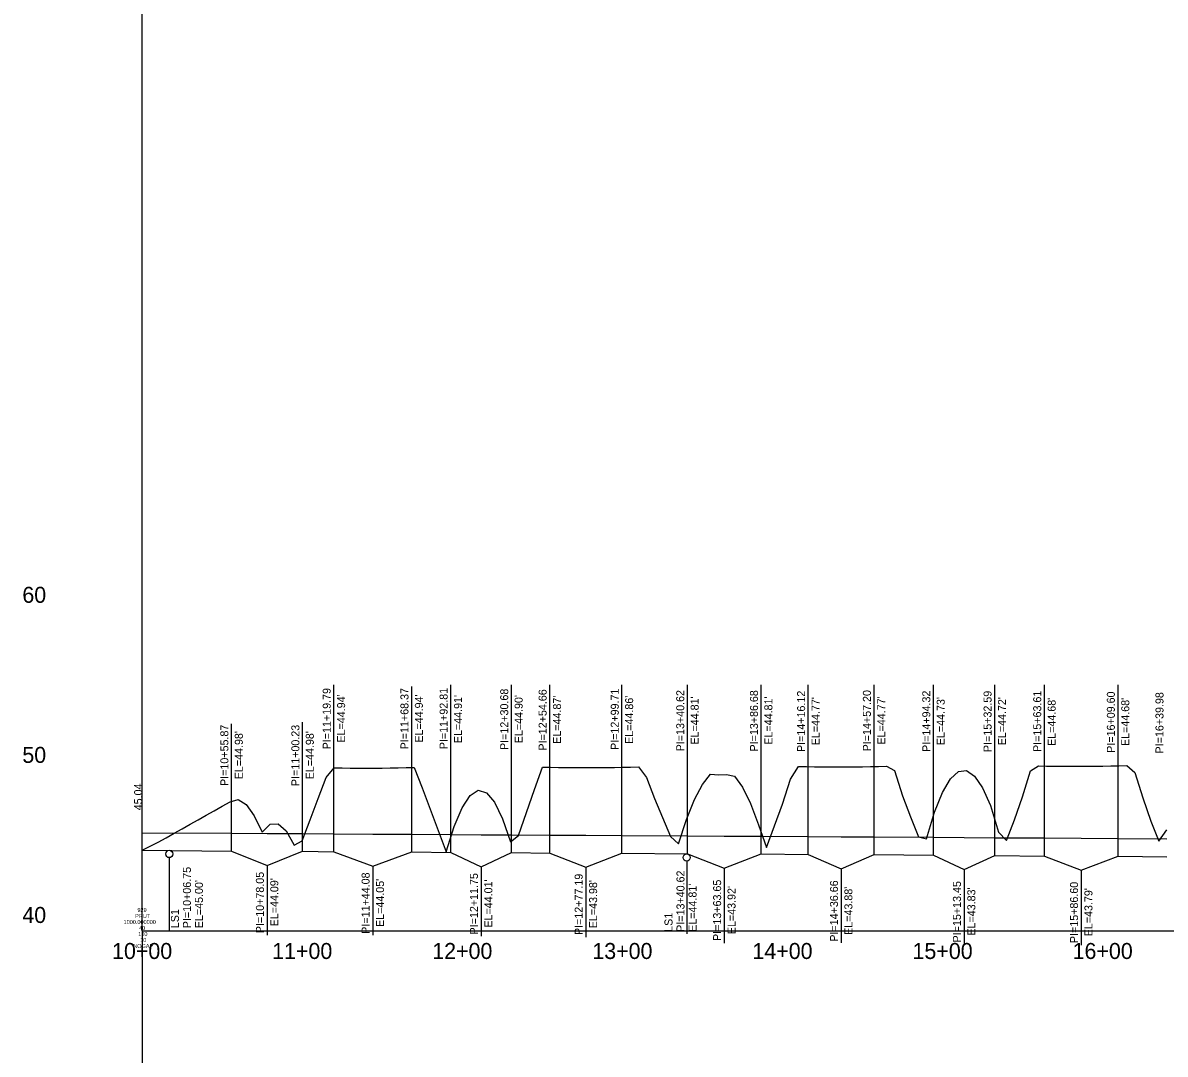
# Model space of a CAD drawing. Extents: x 2394206 to 2397081, y 556531 to 561531.
# Drawn here: x 2394206 to 2394920, y 558954 to 559598 of the extents above; entities that cross this region are included whole.
import ezdxf

# ---------------------------------------------------------------- set-up
doc = ezdxf.new("R2010")
doc.units = 0
for name, color, linetype in [('Default', 7, 'Continuous'), ('Existing ground', 7, 'Continuous'), ('Profile grid', 7, 'Continuous'), ('Proposed bankfull', 7, 'Continuous'), ('Proposed structure lables', 7, 'Continuous'), ('Station lables', 7, 'Continuous')]:
    doc.layers.add(name, color=color, linetype=linetype)

msp = doc.modelspace()

# ---------------------------------------------------------------- linework, layer by layer
at = {"layer": 'Default'}
for p, q in [((2394400.63, 559080.63), (2394400.63, 559185.03)), ((2394449.21, 559080.58), (2394449.21, 559183.93)), ((2394473.65, 559080.25), (2394473.65, 559185.03)), ((2394511.52, 559080.21), (2394511.52, 559185.03)), ((2394535.5, 559079.85), (2394535.5, 559185.03)), ((2394580.55, 559079.8), (2394580.55, 559185.03)), ((2394621.46, 559079.33), (2394621.46, 559185.03)), ((2394667.52, 559079.28), (2394667.52, 559185.03)), ((2394696.96, 559078.91), (2394696.96, 559185.03)), ((2394738.04, 559078.87), (2394738.04, 559185.03)), ((2394775.16, 559078.46), (2394775.16, 559185.03)), ((2394813.43, 559078.42), (2394813.43, 559185.03)), ((2394844.45, 559078.01), (2394844.45, 559185.03)), ((2394890.44, 559077.96), (2394890.44, 559185.03)), ((2394336.71, 559081.03), (2394336.71, 559160.51)), ((2394381.07, 559080.99), (2394381.07, 559161.61)), ((2394358.89, 559072.12), (2394358.89, 559028.6)), ((2394424.92, 559071.73), (2394424.92, 559028.6)), ((2394492.59, 559071.33), (2394492.59, 559028.01)), ((2394558.03, 559070.94), (2394558.03, 559027.42)), ((2394644.49, 559070.42), (2394644.49, 559023.52)), ((2394717.5, 559069.99), (2394717.5, 559023.72)), ((2394794.29, 559069.53), (2394794.29, 559022.54)), ((2394867.44, 559069.1), (2394867.44, 559022.35))]:
    msp.add_line(p, q, dxfattribs=at)
at = {"layer": 'Existing ground'}
for points in [[(2394280.84, 559081.62), (2394285.84, 559084.14), (2394290.84, 559086.66), (2394295.84, 559089.37), (2394300.84, 559092.19), (2394305.84, 559095.01), (2394310.84, 559097.82), (2394315.84, 559100.64), (2394320.84, 559103.46), (2394325.84, 559106.27), (2394330.84, 559109.09), (2394335.84, 559111.91), (2394340.84, 559113.23), (2394345.84, 559110.24), (2394350.84, 559103.04), (2394355.84, 559093.01), (2394360.84, 559097.82), (2394365.84, 559098.04), (2394370.84, 559093.64), (2394375.84, 559084.85), (2394380.84, 559087.52), (2394385.84, 559100.69), (2394390.84, 559113.85), (2394395.84, 559127.01), (2394400.84, 559133.12), (2394405.84, 559133.05), (2394410.84, 559132.99), (2394415.84, 559132.96), (2394420.84, 559132.95), (2394425.84, 559132.96), (2394430.84, 559132.99), (2394435.84, 559133.04), (2394440.84, 559133.12), (2394445.84, 559133.21), (2394450.84, 559133.31), (2394455.84, 559120.68), (2394460.84, 559107.32), (2394465.84, 559093.96), (2394470.84, 559080.67), (2394475.84, 559096.49), (2394480.84, 559108.21), (2394485.84, 559115.86), (2394490.84, 559119.04), (2394495.84, 559117.58), (2394500.84, 559111.57), (2394505.84, 559101.31), (2394510.84, 559086.78), (2394515.84, 559090.82), (2394520.84, 559105.21), (2394525.84, 559119.6), (2394530.84, 559133.52), (2394535.84, 559133.42), (2394540.84, 559133.34), (2394545.84, 559133.27), (2394550.84, 559133.23), (2394555.84, 559133.21), (2394560.84, 559133.22), (2394565.84, 559133.24), (2394570.84, 559133.3), (2394575.84, 559133.37), (2394580.84, 559133.46), (2394585.84, 559133.56), (2394590.84, 559133.66), (2394595.84, 559127.04), (2394600.84, 559113.87), (2394605.84, 559101.99), (2394610.84, 559090.12), (2394615.84, 559085.7), (2394620.84, 559100.88), (2394625.84, 559113.22), (2394630.84, 559122.71), (2394635.84, 559129.04), (2394640.84, 559128.77), (2394645.84, 559128.92), (2394650.84, 559127.98), (2394655.84, 559120.94), (2394660.84, 559110.81), (2394665.84, 559097.42), (2394670.84, 559083.42), (2394675.84, 559096.94), (2394680.84, 559110.46), (2394685.84, 559126.06), (2394690.84, 559133.93), (2394695.84, 559133.84), (2394700.84, 559133.76), (2394705.84, 559133.7), (2394710.84, 559133.66), (2394715.84, 559133.65), (2394720.84, 559133.67), (2394725.84, 559133.71), (2394730.84, 559133.77), (2394735.84, 559133.86), (2394740.84, 559133.96), (2394745.84, 559134.06), (2394750.84, 559131.41), (2394755.84, 559115.64), (2394760.84, 559102.49), (2394765.84, 559090.01), (2394770.84, 559088.69), (2394775.84, 559105.44), (2394780.84, 559117.72)], [(2394780.84, 559117.72), (2394785.84, 559126.23), (2394790.84, 559130.88), (2394795.84, 559131.47), (2394800.84, 559127.99), (2394805.84, 559120.58), (2394810.84, 559109.53), (2394815.84, 559092.82), (2394820.84, 559087.8), (2394825.84, 559100.69), (2394830.84, 559114.92), (2394835.84, 559131.32), (2394840.84, 559134.32), (2394845.84, 559134.24), (2394850.84, 559134.17), (2394855.84, 559134.12), (2394860.84, 559134.1), (2394865.84, 559134.09), (2394870.84, 559134.11), (2394875.84, 559134.15), (2394880.84, 559134.21), (2394885.84, 559134.29), (2394890.84, 559134.39), (2394895.84, 559134.49), (2394900.84, 559130.13), (2394905.84, 559114.33), (2394910.84, 559099.75), (2394915.84, 559087.24), (2394920.84, 559094.41)]]:
    msp.add_lwpolyline(points, dxfattribs=at)
at = {"layer": 'Profile grid'}
for q in [(2394280.84, 561531.18), (2397080.84, 559031.18), (2394280.84, 556531.18)]:
    msp.add_line((2394280.84, 559031.18), q, dxfattribs=at)
at = {"layer": 'Proposed bankfull'}
msp.add_lwpolyline([(2394280.84, 559092.58), (2394336.71, 559092.26), (2394358.89, 559092.13), (2394381.07, 559092), (2394400.63, 559091.88), (2394424.92, 559091.74), (2394449.21, 559091.6), (2394473.65, 559091.45), (2394492.59, 559091.34), (2394511.52, 559091.23), (2394535.5, 559091.09), (2394558.03, 559090.96), (2394580.55, 559090.83), (2394621.46, 559090.59), (2394644.49, 559090.45), (2394667.52, 559090.32), (2394696.96, 559090.14), (2394717.5, 559090.02), (2394738.04, 559089.9), (2394775.16, 559089.69), (2394794.29, 559089.57), (2394813.43, 559089.46), (2394844.45, 559089.28), (2394867.44, 559089.14), (2394890.44, 559089.01), (2394920.82, 559088.83)], dxfattribs=at)
at = {"layer": 'Proposed structure lables'}
for p, q in [((2394280.84, 559081.58), (2394336.71, 559081.03)), ((2394297.76, 559077), (2394297.76, 559031.62)), ((2394336.71, 559081.03), (2394358.89, 559072.12)), ((2394358.89, 559072.12), (2394381.07, 559080.99)), ((2394381.07, 559080.99), (2394400.63, 559080.63)), ((2394400.63, 559080.63), (2394424.92, 559071.73)), ((2394424.92, 559071.73), (2394449.21, 559080.58)), ((2394449.21, 559080.58), (2394473.65, 559080.25)), ((2394473.65, 559080.25), (2394492.59, 559071.33)), ((2394492.59, 559071.33), (2394511.52, 559080.21)), ((2394511.52, 559080.21), (2394535.5, 559079.85)), ((2394535.5, 559079.85), (2394558.03, 559070.94)), ((2394558.03, 559070.94), (2394580.55, 559079.8)), ((2394580.55, 559079.8), (2394621.46, 559079.33)), ((2394620.98, 559074.74), (2394620.98, 559029.37)), ((2394621.46, 559079.33), (2394644.49, 559070.42)), ((2394644.49, 559070.42), (2394667.52, 559079.28)), ((2394667.52, 559079.28), (2394696.96, 559078.91)), ((2394696.96, 559078.91), (2394717.5, 559069.99)), ((2394717.5, 559069.99), (2394738.04, 559078.87)), ((2394738.04, 559078.87), (2394775.16, 559078.46)), ((2394775.16, 559078.46), (2394794.29, 559069.53)), ((2394794.29, 559069.53), (2394813.43, 559078.42)), ((2394813.43, 559078.42), (2394844.45, 559078.01)), ((2394844.45, 559078.01), (2394867.44, 559069.1)), ((2394867.44, 559069.1), (2394890.44, 559077.96)), ((2394890.44, 559077.96), (2394920.82, 559077.56))]:
    msp.add_line(p, q, dxfattribs=at)
for centre in [(2394297.76, 559079.29), (2394620.98, 559077.04)]:
    msp.add_ellipse(centre, major_axis=(0, -2.29), ratio=0.950348, dxfattribs=at)

# ---------------------------------------------------------------- texts
at = {"layer": 'Profile grid'}
for s, height, p in [('     60', 10, (2394187.44, 559236.18)), ('     50', 10, (2394187.44, 559136.18)), ('     40', 10, (2394187.44, 559036.18)), ('PRUT', 2.5, (2394276.47, 559039.31)), ('929', 2.5, (2394277.89, 559043.06)), ('1000.000000', 2.5, (2394269.25, 559035.56)), ('40', 2.5, (2394278.91, 559031.81)), ('100', 2.5, (2394278.4, 559028.06)), ('10', 2.5, (2394279.62, 559024.31)), ('NOGAP', 2.5, (2394275.27, 559020.56))]:
    msp.add_text(s, height=height, dxfattribs=at).set_placement(p)
at = {"layer": 'Proposed structure lables'}
for s, p in [('PI=11+19.79', (2394398.63, 559144.65)), ('PI=11+68.37', (2394447.21, 559144.65)), ('PI=11+92.81', (2394471.65, 559144.74)), ('PI=12+30.68', (2394509.52, 559144.23)), ('PI=12+54.66', (2394533.5, 559143.87)), ('PI=12+99.71', (2394578.55, 559144.29)), ("EL=44.94'", (2394407.63, 559148.9)), ("EL=44.94'", (2394456.21, 559148.85)), ("EL=44.91'", (2394480.65, 559148.52)), ("EL=44.90'", (2394518.52, 559148.48)), ("EL=44.87'", (2394542.5, 559148.11)), ("EL=44.86'", (2394587.55, 559148.07)), ('PI=13+40.62', (2394619.46, 559143.4)), ("EL=44.81'", (2394628.46, 559147.6)), ('PI=13+86.68', (2394665.52, 559143.3)), ("EL=44.81'", (2394674.52, 559147.55)), ('PI=14+16.12', (2394694.96, 559142.97)), ("EL=44.77'", (2394703.96, 559147.17)), ('PI=14+57.20', (2394736.04, 559143.39)), ("EL=44.77'", (2394745.04, 559147.64)), ('PI=14+94.32', (2394773.16, 559143.03)), ("EL=44.73'", (2394782.16, 559147.23)), ('PI=15+32.59', (2394811.43, 559142.94)), ("EL=44.72'", (2394820.43, 559147.19)), ('PI=15+63.61', (2394842.45, 559143)), ("EL=44.68'", (2394851.45, 559146.78)), ('PI=16+09.60', (2394888.44, 559142.49)), ("EL=44.68'", (2394897.44, 559146.73)), ('PI=16+39.98', (2394918.82, 559142.08)), ('PI=10+55.87', (2394334.71, 559121.77)), ("EL=44.98'", (2394343.71, 559125.97)), ('PI=11+00.23', (2394379.07, 559121.68)), ("EL=44.98'", (2394388.07, 559125.93)), ('45.04', (2394280.84, 559106.58)), ('45.04', (2394280.84, 559106.58)), ('PI=10+06.75', (2394311.33, 559032.91)), ('PI=10+78.05', (2394356.89, 559029.83)), ('PI=13+40.62', (2394619.62, 559030.65)), ("EL=45.00'", (2394318.83, 559032.91)), ("EL=44.09'", (2394365.89, 559034.08)), ('PI=11+44.08', (2394422.92, 559029.44)), ("EL=44.05'", (2394431.92, 559033.68)), ('PI=12+11.75', (2394490.59, 559029.04)), ("EL=44.01'", (2394499.59, 559033.28)), ('PI=12+77.19', (2394556.03, 559028.65)), ("EL=43.98'", (2394565.03, 559032.89)), ("EL=44.81'", (2394627.12, 559030.65)), ('PI=13+63.65', (2394642.49, 559024.94)), ('PI=14+36.66', (2394715.5, 559024.5)), ('PI=15+13.45', (2394792.29, 559024.05)), ('PI=15+86.60', (2394865.44, 559023.61)), ("EL=43.92'", (2394651.49, 559029.18)), ("EL=43.88'", (2394724.5, 559028.75)), ("EL=43.83'", (2394801.29, 559028.29)), ("EL=43.79'", (2394874.44, 559027.86)), ('LS1', (2394303.83, 559032.91)), ('LS1', (2394612.12, 559030.65))]:
    msp.add_text(s, height=5, rotation=90, dxfattribs=at).set_placement(p)
at = {"layer": 'Station lables'}
for s, p in [('10+00', (2394262.05, 559013.68)), ('11+00', (2394362.05, 559013.68)), ('12+00', (2394462.05, 559013.68)), ('13+00', (2394562.05, 559013.68)), ('14+00', (2394662.05, 559013.68)), ('15+00', (2394762.05, 559013.68)), ('16+00', (2394862.05, 559013.68))]:
    msp.add_text(s, height=10, dxfattribs=at).set_placement(p)

doc.saveas('drawing.dxf')
